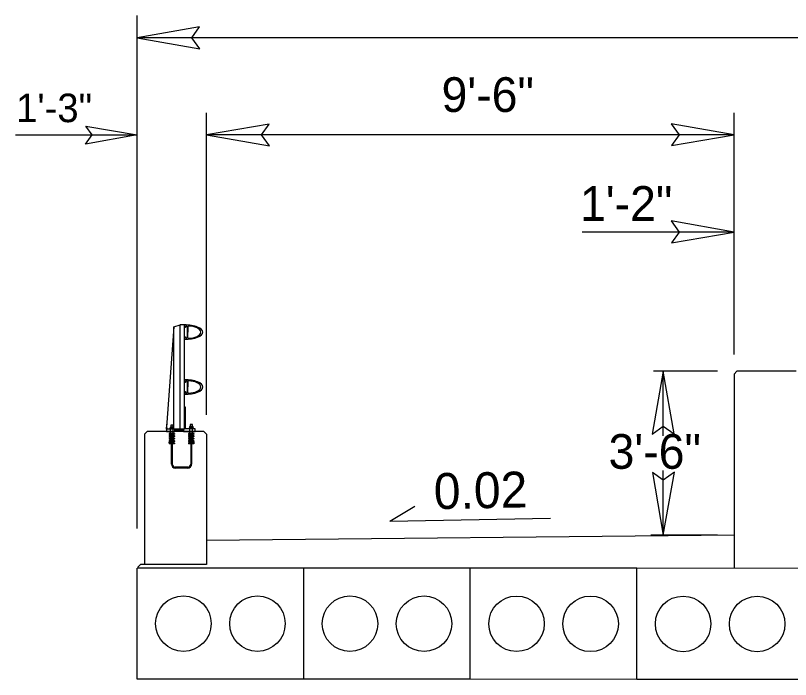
# Model space of a CAD drawing. Extents: x 1733676 to 1734289, y 540979 to 541226.
# Drawn here: x 1734003.85 to 1734017.8, y 541157.15 to 541169.11 of the extents above; entities that cross this region are included whole.
import ezdxf

# ---------------------------------------------------------------- set-up
doc = ezdxf.new("R2010")
doc.units = 0
for name, color, linetype in [('Prop Dimension', 7, 'Continuous'), ('Prop Terminator CELL', 7, 'Continuous'), ('Typical Bridge Rail Two Bar CELL', 7, 'Continuous'), ('Typical Pavement Slope CELL', 7, 'Continuous'), ('Typical Pavement Slope Information CELL', 7, 'Continuous'), ('Typical Slope Point Local CELL', 7, 'Continuous')]:
    doc.layers.add(name, color=color, linetype=linetype)

msp = doc.modelspace()

# ---------------------------------------------------------------- linework, layer by layer
at = {"layer": 'Prop Dimension'}
for p, q in [((1734006.037, 541159.872), (1734006.037, 541169.109)), ((1734051.037, 541168.709), (1734006.037, 541168.709)), ((1734007.287, 541161.919), (1734007.287, 541167.359)), ((1734016.787, 541163.002), (1734016.787, 541167.359)), ((1734003.846, 541166.959), (1734006.037, 541166.959)), ((1734016.787, 541166.959), (1734007.287, 541166.959)), ((1734016.787, 541165.209), (1734014.051, 541165.209)), ((1734016.487, 541162.702), (1734015.336, 541162.702)), ((1734015.513, 541161.54), (1734015.513, 541162.702)), ((1734015.513, 541159.752), (1734015.513, 541160.918)), ((1734016.487, 541159.752), (1734015.287, 541159.752)), ((1734006.036, 541157.159), (1734006.037, 541159.159)), ((1734009.037, 541159.157), (1734006.037, 541159.159)), ((1734009.036, 541157.157), (1734009.037, 541159.157)), ((1734009.036, 541157.157), (1734009.037, 541159.157)), ((1734012.037, 541159.155), (1734009.037, 541159.157)), ((1734012.036, 541157.155), (1734012.037, 541159.155)), ((1734012.036, 541157.155), (1734012.037, 541159.155)), ((1734015.037, 541159.154), (1734012.037, 541159.155)), ((1734015.036, 541157.154), (1734015.037, 541159.154)), ((1734015.036, 541157.154), (1734015.037, 541159.154)), ((1734018.037, 541159.152), (1734015.037, 541159.154)), ((1734009.036, 541157.157), (1734006.036, 541157.159)), ((1734012.036, 541157.155), (1734009.036, 541157.157)), ((1734015.036, 541157.154), (1734012.036, 541157.155)), ((1734018.036, 541157.152), (1734015.036, 541157.154))]:
    msp.add_line(p, q, dxfattribs=at)
for centre in [(1734006.87, 541158.158), (1734008.203, 541158.158), (1734009.87, 541158.157), (1734011.203, 541158.156), (1734012.87, 541158.155), (1734014.203, 541158.154), (1734015.87, 541158.153), (1734017.203, 541158.152)]:
    msp.add_circle(centre, 0.5, dxfattribs=at)
at = {"layer": 'Prop Terminator CELL'}
for points in [[(1734007.162, 541168.902), (1734006.037, 541168.709), (1734007.168, 541168.509), (1734007.024, 541168.709)], [(1734005.111, 541167.118), (1734006.037, 541166.959), (1734005.106, 541166.794), (1734005.224, 541166.959)], [(1734008.412, 541167.152), (1734007.287, 541166.959), (1734008.418, 541166.759), (1734008.274, 541166.959)], [(1734015.662, 541166.765), (1734016.787, 541166.959), (1734015.656, 541167.159), (1734015.799, 541166.959)], [(1734015.662, 541165.015), (1734016.787, 541165.209), (1734015.656, 541165.409), (1734015.799, 541165.209)], [(1734015.707, 541161.577), (1734015.513, 541162.702), (1734015.313, 541161.57), (1734015.513, 541161.714)], [(1734015.319, 541160.877), (1734015.513, 541159.752), (1734015.713, 541160.883), (1734015.513, 541160.739)]]:
    msp.add_lwpolyline(points, close=True, dxfattribs=at)
at = {"layer": 'Typical Bridge Rail Two Bar CELL'}
for p, q in [((1734006.699, 541163.503), (1734006.567, 541161.694)), ((1734006.699, 541163.503), (1734006.813, 541163.54)), ((1734006.699, 541161.657), (1734006.699, 541163.503)), ((1734006.888, 541163.54), (1734006.813, 541163.54)), ((1734006.813, 541161.657), (1734006.813, 541163.54)), ((1734006.888, 541161.657), (1734006.888, 541163.54)), ((1734006.951, 541163.509), (1734006.951, 541163.407)), ((1734006.951, 541163.304), (1734006.951, 541163.407)), ((1734006.699, 541162.639), (1734006.695, 541162.639)), ((1734016.836, 541162.702), (1734016.787, 541162.653)), ((1734016.787, 541162.653), (1734016.787, 541159.153)), ((1734017.905, 541162.702), (1734016.836, 541162.702)), ((1734006.951, 541162.522), (1734006.951, 541162.42)), ((1734006.951, 541162.317), (1734006.951, 541162.42)), ((1734006.567, 541161.657), (1734006.567, 541161.694)), ((1734006.571, 541161.715), (1734006.571, 541161.748)), ((1734006.684, 541161.733), (1734006.641, 541161.733)), ((1734006.641, 541161.733), (1734006.641, 541161.697)), ((1734006.684, 541161.697), (1734006.684, 541161.733)), ((1734006.987, 541161.583), (1734006.987, 541161.666)), ((1734007.033, 541161.743), (1734006.989, 541161.743)), ((1734006.989, 541161.743), (1734006.989, 541161.707)), ((1734007.033, 541161.707), (1734007.033, 541161.743)), ((1734007.035, 541161.583), (1734007.035, 541161.666)), ((1734006.218, 541161.619), (1734006.169, 541161.57)), ((1734006.169, 541161.57), (1734006.169, 541159.225)), ((1734007.238, 541161.619), (1734006.218, 541161.619)), ((1734006.711, 541161.583), (1734006.611, 541161.583)), ((1734006.711, 541161.572), (1734006.611, 541161.572)), ((1734006.652, 541161.538), (1734006.611, 541161.538)), ((1734006.652, 541161.527), (1734006.611, 541161.527)), ((1734006.652, 541161.56), (1734006.633, 541161.56)), ((1734006.652, 541161.549), (1734006.633, 541161.549)), ((1734006.64, 541161.573), (1734006.64, 541161.657)), ((1734006.669, 541161.561), (1734006.652, 541161.561)), ((1734006.652, 541161.561), (1734006.652, 541161.03)), ((1734006.669, 541161.561), (1734006.669, 541161.03)), ((1734006.689, 541161.56), (1734006.669, 541161.56)), ((1734006.689, 541161.549), (1734006.669, 541161.549)), ((1734006.711, 541161.538), (1734006.669, 541161.538)), ((1734006.711, 541161.527), (1734006.669, 541161.527)), ((1734006.683, 541161.573), (1734006.683, 541161.657)), ((1734007.059, 541161.583), (1734006.959, 541161.583)), ((1734007.059, 541161.572), (1734006.959, 541161.572)), ((1734007.001, 541161.538), (1734006.959, 541161.538)), ((1734007.001, 541161.527), (1734006.959, 541161.527)), ((1734007.001, 541161.56), (1734006.982, 541161.56)), ((1734007.001, 541161.549), (1734006.982, 541161.549)), ((1734007.001, 541161.561), (1734007.001, 541161.03)), ((1734007.018, 541161.56), (1734007.001, 541161.56)), ((1734007.018, 541161.561), (1734007.018, 541161.03)), ((1734007.037, 541161.56), (1734007.018, 541161.56)), ((1734007.037, 541161.549), (1734007.018, 541161.549)), ((1734007.059, 541161.538), (1734007.018, 541161.538)), ((1734007.059, 541161.527), (1734007.018, 541161.527)), ((1734007.287, 541161.57), (1734007.238, 541161.619)), ((1734007.287, 541161.57), (1734007.287, 541159.225)), ((1734006.652, 541161.494), (1734006.611, 541161.494)), ((1734006.652, 541161.483), (1734006.611, 541161.483)), ((1734006.652, 541161.449), (1734006.611, 541161.449)), ((1734006.652, 541161.438), (1734006.611, 541161.438)), ((1734006.652, 541161.405), (1734006.611, 541161.405)), ((1734006.652, 541161.394), (1734006.611, 541161.394)), ((1734006.652, 541161.516), (1734006.633, 541161.516)), ((1734006.652, 541161.505), (1734006.633, 541161.505)), ((1734006.652, 541161.472), (1734006.633, 541161.472)), ((1734006.652, 541161.46), (1734006.633, 541161.46)), ((1734006.652, 541161.427), (1734006.633, 541161.427)), ((1734006.652, 541161.416), (1734006.633, 541161.416)), ((1734006.689, 541161.516), (1734006.669, 541161.516)), ((1734006.689, 541161.505), (1734006.669, 541161.505)), ((1734006.711, 541161.494), (1734006.669, 541161.494)), ((1734006.711, 541161.483), (1734006.669, 541161.483)), ((1734006.689, 541161.472), (1734006.669, 541161.472)), ((1734006.689, 541161.46), (1734006.669, 541161.46)), ((1734006.711, 541161.449), (1734006.669, 541161.449)), ((1734006.711, 541161.438), (1734006.669, 541161.438)), ((1734006.689, 541161.427), (1734006.669, 541161.427)), ((1734006.689, 541161.416), (1734006.669, 541161.416)), ((1734006.711, 541161.405), (1734006.669, 541161.405)), ((1734006.711, 541161.394), (1734006.669, 541161.394)), ((1734007.001, 541161.494), (1734006.959, 541161.494)), ((1734007.001, 541161.483), (1734006.959, 541161.483)), ((1734007.001, 541161.449), (1734006.959, 541161.449)), ((1734007.001, 541161.438), (1734006.959, 541161.438)), ((1734007.001, 541161.405), (1734006.959, 541161.405)), ((1734007.001, 541161.394), (1734006.959, 541161.394)), ((1734007.001, 541161.516), (1734006.982, 541161.516)), ((1734007.001, 541161.505), (1734006.982, 541161.505)), ((1734007.001, 541161.472), (1734006.982, 541161.472)), ((1734007.001, 541161.46), (1734006.982, 541161.46)), ((1734007.001, 541161.427), (1734006.982, 541161.427)), ((1734007.001, 541161.416), (1734006.982, 541161.416)), ((1734007.037, 541161.516), (1734007.018, 541161.516)), ((1734007.037, 541161.505), (1734007.018, 541161.505)), ((1734007.059, 541161.494), (1734007.018, 541161.494)), ((1734007.059, 541161.483), (1734007.018, 541161.483)), ((1734007.037, 541161.472), (1734007.018, 541161.472)), ((1734007.037, 541161.46), (1734007.018, 541161.46)), ((1734007.059, 541161.449), (1734007.018, 541161.449)), ((1734007.059, 541161.438), (1734007.018, 541161.438)), ((1734007.037, 541161.427), (1734007.018, 541161.427)), ((1734007.037, 541161.416), (1734007.018, 541161.416)), ((1734007.059, 541161.405), (1734007.018, 541161.405)), ((1734007.059, 541161.394), (1734007.018, 541161.394)), ((1734006.948, 541160.977), (1734006.723, 541160.977)), ((1734006.948, 541160.96), (1734006.723, 541160.96)), ((1734006.049, 541159.172), (1734006.097, 541159.225)), ((1734006.178, 541159.225), (1734006.097, 541159.225)), ((1734007.287, 541159.225), (1734006.178, 541159.225))]:
    msp.add_line(p, q, dxfattribs=at)
for points in [[(1734006.888, 541163.276), (1734006.888, 541163.325), (1734006.908, 541163.325), (1734006.908, 541163.317), (1734006.906, 541163.317), (1734006.906, 541163.296), (1734006.939, 541163.296), (1734006.943, 541163.328), (1734006.943, 541163.407), (1734006.943, 541163.485), (1734006.939, 541163.517), (1734006.906, 541163.517), (1734006.906, 541163.496), (1734006.908, 541163.496), (1734006.908, 541163.488), (1734006.888, 541163.488), (1734006.888, 541163.537)], [(1734006.888, 541162.289), (1734006.888, 541162.338), (1734006.908, 541162.338), (1734006.908, 541162.33), (1734006.906, 541162.33), (1734006.906, 541162.309), (1734006.939, 541162.309), (1734006.943, 541162.341), (1734006.943, 541162.42), (1734006.943, 541162.498), (1734006.939, 541162.529), (1734006.906, 541162.529), (1734006.906, 541162.509), (1734006.908, 541162.509), (1734006.908, 541162.501), (1734006.888, 541162.501), (1734006.888, 541162.55)], [(1734007.081, 541161.619), (1734007.081, 541161.666), (1734006.907, 541161.666), (1734006.907, 541162.053), (1734006.888, 541162.053), (1734006.888, 541161.657), (1734006.576, 541161.657), (1734006.576, 541161.684), (1734006.567, 541161.684), (1734006.567, 541161.619), (1734006.718, 541161.619), (1734006.718, 541161.645), (1734006.869, 541161.645), (1734006.869, 541161.619), (1734007.081, 541161.619)], [(1734006.705, 541161.656), (1734006.705, 541161.665), (1734006.662, 541161.665), (1734006.619, 541161.665), (1734006.619, 541161.656)], [(1734006.694, 541161.665), (1734006.694, 541161.692), (1734006.688, 541161.697), (1734006.636, 541161.697), (1734006.63, 541161.692), (1734006.63, 541161.665), (1734006.694, 541161.665), (1734006.673, 541161.665), (1734006.673, 541161.692), (1734006.678, 541161.697), (1734006.673, 541161.692), (1734006.668, 541161.697), (1734006.657, 541161.697), (1734006.651, 541161.692), (1734006.651, 541161.665), (1734006.651, 541161.692), (1734006.646, 541161.697)], [(1734007.055, 541161.666), (1734007.055, 541161.674), (1734007.012, 541161.674), (1734006.968, 541161.674), (1734006.968, 541161.666)], [(1734007.043, 541161.674), (1734007.043, 541161.701), (1734007.038, 541161.707), (1734006.984, 541161.707), (1734006.979, 541161.701), (1734006.979, 541161.674), (1734007.043, 541161.674), (1734007.021, 541161.674), (1734007.021, 541161.701), (1734007.027, 541161.707), (1734007.021, 541161.701), (1734007.016, 541161.707), (1734007.005, 541161.707), (1734007, 541161.701), (1734007, 541161.674), (1734007, 541161.701), (1734006.995, 541161.707)], [(1734006.611, 541161.583), (1734006.611, 541161.572), (1734006.633, 541161.56), (1734006.633, 541161.549), (1734006.611, 541161.538), (1734006.611, 541161.527), (1734006.633, 541161.516), (1734006.633, 541161.505), (1734006.611, 541161.494), (1734006.611, 541161.483), (1734006.633, 541161.472), (1734006.633, 541161.46), (1734006.611, 541161.449), (1734006.611, 541161.438), (1734006.633, 541161.427), (1734006.633, 541161.416), (1734006.611, 541161.405), (1734006.611, 541161.394)], [(1734006.711, 541161.583), (1734006.711, 541161.572), (1734006.689, 541161.56), (1734006.689, 541161.549), (1734006.711, 541161.538), (1734006.711, 541161.527), (1734006.689, 541161.516), (1734006.689, 541161.505), (1734006.711, 541161.494), (1734006.711, 541161.483), (1734006.689, 541161.472), (1734006.689, 541161.46), (1734006.711, 541161.449), (1734006.711, 541161.438), (1734006.689, 541161.427), (1734006.689, 541161.416), (1734006.711, 541161.405), (1734006.711, 541161.394)], [(1734006.959, 541161.583), (1734006.959, 541161.572), (1734006.982, 541161.56), (1734006.982, 541161.549), (1734006.959, 541161.538), (1734006.959, 541161.527), (1734006.982, 541161.516), (1734006.982, 541161.505), (1734006.959, 541161.494), (1734006.959, 541161.483), (1734006.982, 541161.472), (1734006.982, 541161.46), (1734006.959, 541161.449), (1734006.959, 541161.438), (1734006.982, 541161.427), (1734006.982, 541161.416), (1734006.959, 541161.405), (1734006.959, 541161.394)], [(1734007.06, 541161.583), (1734007.06, 541161.572), (1734007.037, 541161.56), (1734007.037, 541161.549), (1734007.06, 541161.538), (1734007.06, 541161.527), (1734007.037, 541161.516), (1734007.037, 541161.505), (1734007.06, 541161.494), (1734007.06, 541161.483), (1734007.037, 541161.472), (1734007.037, 541161.46), (1734007.06, 541161.449), (1734007.06, 541161.438), (1734007.037, 541161.427), (1734007.037, 541161.416), (1734007.06, 541161.405), (1734007.06, 541161.394)]]:
    msp.add_lwpolyline(points, dxfattribs=at)
for centre in [(1734006.62, 541161.422), (1734007.051, 541161.422)]:
    msp.add_circle(centre, 0.00834, dxfattribs=at)
for centre, radius, start, end in [((1734006.959, 541163.509), 0.00783, 90, 180), ((1734006.959, 541163.304), 0.00783, 180, 270), ((1734006.959, 541162.522), 0.00783, 90, 180), ((1734006.959, 541162.317), 0.00783, 180, 270), ((1734006.723, 541161.03), 0.07, 180, 270), ((1734006.723, 541161.03), 0.0534, 180, 270), ((1734006.948, 541161.03), 0.0534, 270, 0), ((1734006.948, 541161.03), 0.07, 270, 0)]:
    msp.add_arc(centre, radius, start, end, dxfattribs=at)
for centre, major_axis, ratio, start_param, end_param in [((1734006.888, 541163.407), (0.334, 0), 0.39036, 6.282787, 7.853967), ((1734006.959, 541163.407), (0.222, 0), 0.495501, 6.282718, 7.853881), ((1734006.888, 541163.407), (0.334, 0), 0.39036, 4.712404, 6.282787), ((1734006.959, 541163.407), (0.222, 0), 0.495501, 4.712489, 6.282718), ((1734006.888, 541162.419), (0.334, 0), 0.39036, 6.282787, 7.853967), ((1734006.959, 541162.419), (0.222, 0), 0.495501, 6.282718, 7.853881), ((1734006.888, 541162.419), (0.334, 0), 0.39036, 4.712404, 6.282787), ((1734006.959, 541162.419), (0.222, 0), 0.495501, 4.712489, 6.282718)]:
    msp.add_ellipse(centre, major_axis=major_axis, ratio=ratio, start_param=start_param, end_param=end_param, dxfattribs=at)
at = {"layer": 'Typical Pavement Slope CELL'}
msp.add_line((1734016.787, 541159.752), (1734007.287, 541159.654), dxfattribs=at)
at = {"layer": 'Typical Pavement Slope Information CELL'}
for q in [(1734011.039, 541160.273), (1734013.484, 541160.059)]:
    msp.add_line((1734010.589, 541160.001), q, dxfattribs=at)

# ---------------------------------------------------------------- texts
msp.add_text('0.02', height=0.6476, rotation=1.1457, dxfattribs=at).set_placement((1734011.385, 541160.218))
at = {"layer": 'Typical Slope Point Local CELL'}
for s, height, p in [('9\'-6"', 0.6249, (1734011.519, 541167.372)), ('1\'-3"', 0.5141, (1734003.857, 541167.188)), ('1\'-2"', 0.6249, (1734014.012, 541165.411)), ('3\'-6"', 0.6249, (1734014.527, 541160.946))]:
    msp.add_text(s, height=height, rotation=360, dxfattribs=at).set_placement(p)

doc.saveas('drawing.dxf')
